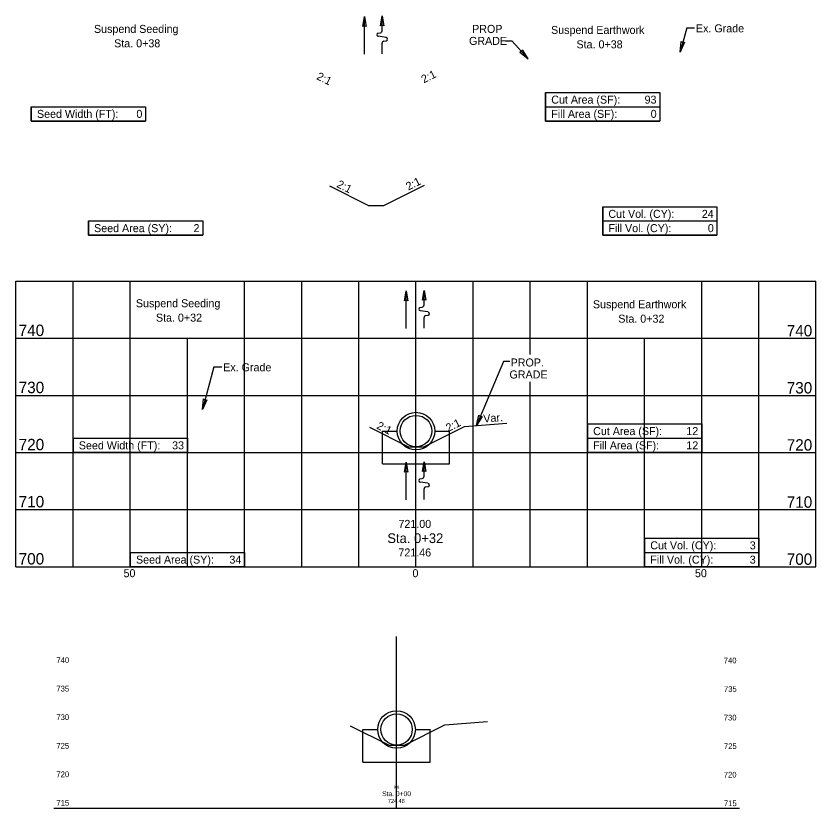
# Model space of a CAD drawing. Extents: x -70 to 515, y 642 to 823.
# Drawn here: x -70 to 70, y 657.8 to 796.4 of the extents above; entities that cross this region are included whole.
import ezdxf

# ---------------------------------------------------------------- set-up
doc = ezdxf.new("R2010")
doc.units = 0
for name, color, linetype in [('Default', 7, 'Continuous'), ('DR_P_Culvert', 7, 'Continuous'), ('DR_P_Headwall', 7, 'Continuous'), ('DT_X_Contour_Major', 7, 'Continuous'), ('DT_X_Spot_Elev', 7, 'Continuous'), ('SH_Data', 7, 'Continuous'), ('SH_Major_Grid_Line', 7, 'Continuous'), ('SH_Text', 7, 'Continuous'), ('XS_P_Finished_Grade', 7, 'Continuous')]:
    doc.layers.add(name, color=color, linetype=linetype)

msp = doc.modelspace()

# ---------------------------------------------------------------- linework, layer by layer
at = {"layer": 'DR_P_Culvert'}
for centre, radius in [((0, 723.75), 3.29), ((0, 723.75), 2.75), ((-3.4, 671.51), 3.29), ((-3.4, 671.51), 2.75)]:
    msp.add_circle(centre, radius, dxfattribs=at)
at = {"layer": 'DR_P_Headwall'}
for p, q in [((-5.88, 723.75), (-3.29, 723.75)), ((-5.88, 718), (-5.88, 723.75)), ((3.29, 723.75), (5.87, 723.75)), ((5.87, 718), (5.87, 723.75)), ((-5.88, 718), (5.87, 718)), ((-9.28, 665.76), (-9.28, 671.51)), ((-9.28, 671.51), (-6.69, 671.51)), ((-0.11, 671.51), (2.47, 671.51)), ((2.47, 665.76), (2.47, 671.51)), ((-9.28, 665.76), (2.47, 665.76))]:
    msp.add_line(p, q, dxfattribs=at)
at = {"layer": 'DT_X_Contour_Major'}
for p, q in [((-9.32, 794.6), (-9.03, 796.33)), ((-9.03, 796.33), (-8.74, 794.59)), ((-9.03, 789.71), (-9.03, 796.33)), ((-6.21, 794.69), (-5.92, 796.42)), ((-5.92, 796.42), (-5.63, 794.68)), ((-5.92, 793.86), (-5.92, 796.42)), ((-9.32, 794.6), (-9.32, 794.6)), ((-8.74, 794.59), (-8.74, 794.6)), ((-6.21, 794.69), (-6.21, 794.69)), ((-5.63, 794.68), (-5.63, 794.68)), ((47.37, 794.35), (46.23, 790.11)), ((47.37, 794.35), (48.76, 794.35)), ((-6.63, 793.41), (-6.23, 793.49)), ((-5.23, 792.65), (-6.62, 792.86)), ((-5.92, 789.8), (-5.92, 791.65)), ((-5.62, 792.02), (-5.22, 792.09)), ((15.65, 792.06), (16.8, 792.06)), ((16.8, 792.06), (19.61, 788.92)), ((46.23, 790.11), (46.42, 791.98)), ((47.01, 791.82), (46.23, 790.11)), ((46.42, 791.98), (46.42, 791.98)), ((47.01, 791.82), (47.01, 791.82)), ((18.15, 790.1), (18.15, 790.1)), ((18.15, 790.1), (19.61, 788.92)), ((19.61, 788.92), (18.61, 790.52)), ((18.61, 790.52), (18.61, 790.51)), ((-1.99, 746.57), (-1.7, 748.31)), ((-1.7, 748.31), (-1.41, 746.57)), ((-1.7, 741.69), (-1.7, 748.31)), ((1.12, 746.66), (1.41, 748.39)), ((1.41, 748.39), (1.7, 746.65)), ((1.41, 745.83), (1.41, 748.39)), ((-1.99, 746.57), (-1.99, 746.57)), ((-1.41, 746.57), (-1.41, 746.57)), ((1.12, 746.66), (1.12, 746.66)), ((1.7, 746.65), (1.7, 746.66)), ((0.7, 745.39), (1.1, 745.46)), ((2.1, 744.62), (0.71, 744.83)), ((1.41, 741.77), (1.41, 743.62)), ((1.71, 743.99), (2.11, 744.07)), ((-35.37, 735), (-37.37, 727.51)), ((-35.37, 735), (-33.98, 735)), ((15.3, 735.94), (10.57, 724.72)), ((16.4, 735.94), (15.3, 735.94)), ((-37.37, 727.51), (-37.19, 729.38)), ((-36.6, 729.21), (-37.37, 727.51)), ((-37.19, 729.38), (-37.19, 729.38)), ((-36.6, 729.21), (-36.6, 729.21)), ((10.57, 724.72), (11, 726.55)), ((11.57, 726.31), (10.57, 724.72)), ((11, 726.55), (11, 726.55)), ((11.57, 726.31), (11.57, 726.31)), ((-1.99, 716.57), (-1.7, 718.31)), ((-1.7, 718.31), (-1.41, 716.57)), ((-1.7, 711.69), (-1.7, 718.31)), ((1.12, 716.66), (1.41, 718.39)), ((1.41, 718.39), (1.7, 716.65)), ((1.41, 715.83), (1.41, 718.39)), ((-1.99, 716.57), (-1.99, 716.57)), ((-1.41, 716.57), (-1.41, 716.57)), ((0.7, 715.39), (1.1, 715.46)), ((1.12, 716.66), (1.12, 716.66)), ((1.7, 716.65), (1.7, 716.66)), ((2.1, 714.62), (0.71, 714.83)), ((1.71, 713.99), (2.11, 714.07)), ((1.41, 711.77), (1.41, 713.62))]:
    msp.add_line(p, q, dxfattribs=at)
for centre, radius, start, end in [((-9.03, 794.16), 0.527, 56.178, 122.8588), ((-6.3, 793.86), 0.375, 280.6197, 360), ((-5.93, 794.24), 0.527, 56.178, 122.8588), ((-6.57, 793.14), 0.281, 100.6197, 261.4692), ((-5.27, 792.37), 0.281, 280.6197, 81.4692), ((-5.55, 791.65), 0.375, 100.6197, 180), ((46.84, 792.35), 0.563, 221.2079, 287.8887), ((18.07, 790.66), 0.563, 278.7189, 345.3996), ((-1.7, 746.13), 0.527, 56.178, 122.8588), ((1.4, 746.22), 0.527, 56.178, 122.8588), ((0.75, 745.11), 0.281, 100.6197, 261.4692), ((1.03, 745.83), 0.375, 280.6197, 360), ((1.78, 743.62), 0.375, 100.6197, 180), ((2.06, 744.34), 0.281, 280.6197, 81.4692), ((-36.77, 729.75), 0.563, 221.2079, 287.8887), ((11.47, 726.86), 0.563, 213.5947, 280.2755), ((-1.7, 716.13), 0.527, 56.178, 122.8588), ((1.03, 715.83), 0.375, 280.6197, 360), ((1.4, 716.22), 0.527, 56.178, 122.8588), ((0.75, 715.11), 0.281, 100.6197, 261.4692), ((2.06, 714.34), 0.281, 280.6197, 81.4692), ((1.78, 713.62), 0.375, 100.6197, 180)]:
    msp.add_arc(centre, radius, start, end, dxfattribs=at)
at = {"layer": 'DT_X_Spot_Elev'}
for points in [[(22.67, 783.03), (42.67, 783.03), (42.67, 778.03), (22.67, 778.03)], [(-67.33, 780.53), (-47.33, 780.53), (-47.33, 778.03), (-67.33, 778.03)], [(32.67, 763.03), (52.67, 763.03), (52.67, 758.03), (32.67, 758.03)], [(-57.33, 760.53), (-37.33, 760.53), (-37.33, 758.03), (-57.33, 758.03)], [(30, 725), (50, 725), (50, 720), (30, 720)], [(-60, 722.5), (-40, 722.5), (-40, 720), (-60, 720)], [(40, 705), (60, 705), (60, 700), (40, 700)], [(-50, 702.5), (-30, 702.5), (-30, 700), (-50, 700)]]:
    msp.add_lwpolyline(points, close=True, dxfattribs=at)
at = {"layer": 'SH_Data'}
for p, q in [((22.67, 783.03), (42.67, 783.03)), ((22.67, 783.03), (22.67, 778.03)), ((42.67, 783.03), (42.67, 778.03)), ((-67.33, 780.53), (-47.33, 780.53)), ((-67.33, 780.53), (-67.33, 778.03)), ((-47.33, 780.53), (-47.33, 778.03)), ((22.67, 780.53), (42.67, 780.53)), ((-67.33, 778.03), (-47.33, 778.03)), ((22.67, 778.03), (42.67, 778.03)), ((32.67, 763.03), (52.67, 763.03)), ((32.67, 763.03), (32.67, 758.03)), ((52.67, 763.03), (52.67, 758.03)), ((-57.33, 760.53), (-37.33, 760.53)), ((-57.33, 760.53), (-57.33, 758.03)), ((-37.33, 760.53), (-37.33, 758.03)), ((32.67, 760.53), (52.67, 760.53)), ((-57.33, 758.03), (-37.33, 758.03)), ((32.67, 758.03), (52.67, 758.03)), ((30, 725), (50, 725)), ((30, 725), (30, 720)), ((50, 725), (50, 720)), ((-60, 722.5), (-40, 722.5)), ((-60, 722.5), (-60, 720)), ((-40, 722.5), (-40, 720)), ((30, 722.5), (50, 722.5)), ((-60, 720), (-40, 720)), ((30, 720), (50, 720)), ((40, 705), (60, 705)), ((40, 705), (40, 700)), ((60, 705), (60, 700)), ((-50, 702.5), (-30, 702.5)), ((-50, 702.5), (-50, 700)), ((-30, 702.5), (-30, 700)), ((40, 702.5), (60, 702.5)), ((-50, 700), (-30, 700)), ((40, 700), (60, 700))]:
    msp.add_line(p, q, dxfattribs=at)
at = {"layer": 'SH_Major_Grid_Line'}
for p, q in [((-70, 750), (70, 750)), ((-70, 700), (-70, 750)), ((-60, 700), (-60, 750)), ((-50, 700), (-50, 750)), ((-30, 700), (-30, 750)), ((-20, 700), (-20, 750)), ((-10, 700), (-10, 750)), ((0, 700), (0, 750)), ((10, 700), (10, 750)), ((20, 737.18), (20, 750)), ((30, 700), (30, 750)), ((50, 700), (50, 750)), ((60, 700), (60, 750)), ((70, 700), (70, 750)), ((-70, 740), (70, 740)), ((-40, 700), (-40, 740)), ((40, 700), (40, 740)), ((20, 700), (20, 732.38)), ((-70, 730), (70, 730)), ((-70, 720), (70, 720)), ((-70, 710), (70, 710)), ((-70, 700), (70, 700)), ((-3.4, 657.76), (-3.4, 687.76)), ((-63.4, 657.76), (56.6, 657.76))]:
    msp.add_line(p, q, dxfattribs=at)
at = {"layer": 'XS_P_Finished_Grade'}
for p, q in [((-8.36, 763.27), (-15.05, 766.62)), ((-5.61, 763.27), (1.48, 766.82)), ((-8.36, 763.27), (-5.61, 763.27)), ((-1.37, 721), (-8.07, 724.35)), ((1.38, 721), (8.46, 724.54)), ((8.46, 724.54), (15.91, 725.16)), ((-1.37, 721), (1.38, 721)), ((-4.78, 668.76), (-11.47, 672.11)), ((-2.03, 668.76), (5.06, 672.3)), ((5.06, 672.3), (12.51, 672.93)), ((-4.78, 668.76), (-2.03, 668.76))]:
    msp.add_line(p, q, dxfattribs=at)

# ---------------------------------------------------------------- texts
at = {"layer": 'Default'}
for s, height, p in [('740', 2, (-69.53, 740.39)), ('740', 2, (64.88, 740.33)), ('730', 2, (-69.53, 730.39)), ('730', 2, (64.88, 730.33)), ('720', 2, (-69.53, 720.39)), ('720', 2, (64.88, 720.33)), ('710', 2, (-69.53, 710.39)), ('710', 2, (64.88, 710.33)), ('700', 2, (-69.53, 700.39)), ('700', 2, (64.88, 700.33)), ('740', 1, (-62.93, 683.16)), ('740', 1, (53.86, 683.09)), ('735', 1, (-62.93, 678.16)), ('735', 1, (53.89, 678.09)), ('730', 1, (-62.93, 673.16)), ('730', 1, (53.86, 673.09)), ('725', 1, (-62.93, 668.16)), ('725', 1, (53.89, 668.09)), ('720', 1, (-62.93, 663.16)), ('720', 1, (53.86, 663.09)), ('715', 1, (-62.93, 658.16)), ('715', 1, (53.89, 658.09))]:
    msp.add_text(s, height=height, dxfattribs=at).set_placement(p)
at = {"layer": 'DT_X_Contour_Major'}
for s, p in [('PROP', (9.82, 793.46)), ('Ex. Grade', (48.99, 793.56)), ('GRADE', (9.28, 791.36)), ('PROP.', (16.56, 735.06)), ('Ex. Grade', (-33.74, 734.22)), ('GRADE', (16.36, 732.96))]:
    msp.add_text(s, height=1.4, dxfattribs=at).set_placement(p)
for s, rotation, p in [('2:1', 26.5651, (1.35, 784.62)), ('2:1', 333.4349, (-17.52, 785.4)), ('2:1', 333.4349, (-13.99, 766.52)), ('2:1', 26.5651, (-1.33, 765.85)), ('Var.', 4.7636, (11.84, 725.21)), ('2:1', 333.4349, (-7.01, 724.24)), ('2:1', 26.5651, (5.65, 723.58))]:
    msp.add_text(s, height=1.4, rotation=rotation, dxfattribs=at).set_placement(p)
at = {"layer": 'SH_Text'}
for s, height, p in [('Suspend Seeding', 1.4, (-56.35, 793.46)), ('Suspend Earthwork', 1.4, (23.64, 793.28)), ('Sta. 0+38', 1.4, (-52.82, 790.94)), ('Sta. 0+38', 1.4, (28.09, 790.76)), ('Cut Area (SF):', 1.4, (23.67, 781.08)), ('93', 1.4, (40, 781.08)), ('Seed Width (FT):', 1.4, (-66.33, 778.58)), ('0', 1.4, (-48.93, 778.58)), ('Fill Area (SF):', 1.4, (23.67, 778.58)), ('0', 1.4, (41.07, 778.58)), ('Cut Vol. (CY):', 1.4, (33.67, 761.08)), ('24', 1.4, (50.02, 761.08)), ('Seed Area (SY):', 1.4, (-56.33, 758.58)), ('2', 1.4, (-38.93, 758.58)), ('Fill Vol. (CY):', 1.4, (33.67, 758.58)), ('0', 1.4, (51.07, 758.58)), ('Suspend Seeding', 1.4, (-49.02, 745.43)), ('Suspend Earthwork', 1.4, (30.96, 745.25)), ('Sta. 0+32', 1.4, (-45.51, 742.91)), ('Sta. 0+32', 1.4, (35.4, 742.73)), ('Cut Area (SF):', 1.4, (31, 723.05)), ('12', 1.4, (47.31, 723.05)), ('Seed Width (FT):', 1.4, (-59, 720.55)), ('33', 1.4, (-42.68, 720.55)), ('Fill Area (SF):', 1.4, (31, 720.55)), ('12', 1.4, (47.31, 720.55)), ('721.00', 1.4, (-3.07, 706.8)), ('Sta. 0+32', 1.7, (-5.02, 704.15)), ('Cut Vol. (CY):', 1.4, (41, 703.05)), ('3', 1.4, (58.41, 703.05)), ('721.46', 1.4, (-3.08, 701.8)), ('Seed Area (SY):', 1.4, (-49, 700.55)), ('34', 1.4, (-32.65, 700.55)), ('Fill Vol. (CY):', 1.4, (41, 700.55)), ('3', 1.4, (58.41, 700.55)), ('50', 1.4, (-51.18, 698.17)), ('0', 1.4, (-0.62, 698.17)), ('50', 1.4, (48.82, 698.17)), ('xx', 0.7, (-3.89, 661.16)), ('Sta. 0+00', 0.85, (-5.93, 659.84)), ('724.48', 0.7, (-4.93, 658.66))]:
    msp.add_text(s, height=height, dxfattribs=at).set_placement(p)

doc.saveas('drawing.dxf')
